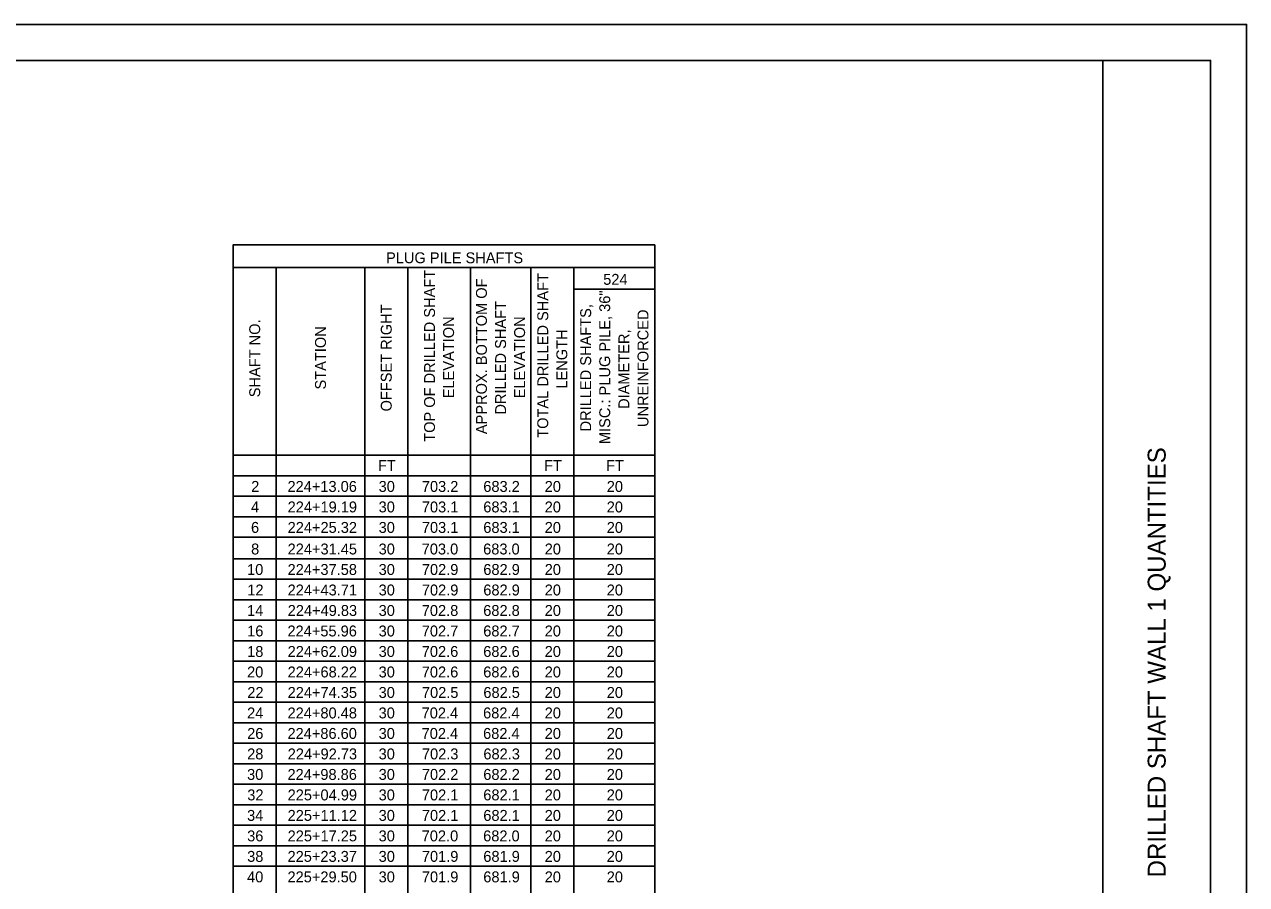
# Model space of a CAD drawing. Extents: x 0 to 34, y 0 to 22.
# Drawn here: x 17 to 34, y 10.04 to 22 of the extents above; entities that cross this region are included whole.
import ezdxf

# ---------------------------------------------------------------- set-up
doc = ezdxf.new("R2010")
doc.units = 0
for name, color, linetype in [('SH_Border', 7, 'Continuous'), ('SH_Cut_Line', 7, 'Continuous'), ('SH_Data', 7, 'Continuous'), ('SH_Text', 7, 'Continuous')]:
    doc.layers.add(name, color=color, linetype=linetype)

msp = doc.modelspace()

# ---------------------------------------------------------------- linework, layer by layer
at = {"layer": 'SH_Border'}
msp.add_line((32, 0.5), (32, 21.5), dxfattribs=at)
msp.add_lwpolyline([(1.5, 21.5), (33.5, 21.5), (33.5, 0.5), (1.5, 0.5)], close=True, dxfattribs=at)
at = {"layer": 'SH_Cut_Line'}
msp.add_lwpolyline([(0, 0), (34, 0), (34, 22), (0, 22)], close=True, dxfattribs=at)
at = {"layer": 'SH_Text'}
for p, q in [((19.903, 18.934), (25.768, 18.934)), ((19.903, 18.934), (19.903, 3.244)), ((25.768, 18.934), (25.768, 3.244)), ((19.903, 18.619), (25.768, 18.619)), ((20.503, 18.619), (20.503, 3.559)), ((21.733, 18.619), (21.733, 3.559)), ((22.333, 18.619), (22.333, 3.559)), ((23.203, 18.619), (23.203, 3.559)), ((24.043, 18.619), (24.043, 3.559)), ((24.643, 18.619), (24.643, 3.244)), ((24.643, 18.319), (25.768, 18.319)), ((19.903, 16.009), (25.768, 16.009)), ((19.903, 15.724), (25.768, 15.724)), ((19.903, 15.439), (25.768, 15.439)), ((19.903, 15.154), (25.768, 15.154)), ((19.903, 14.869), (25.768, 14.869)), ((19.903, 14.569), (25.768, 14.569)), ((19.903, 14.284), (25.768, 14.284)), ((19.903, 13.999), (25.768, 13.999)), ((19.903, 13.714), (25.768, 13.714)), ((19.903, 13.429), (25.768, 13.429)), ((19.903, 13.144), (25.768, 13.144)), ((19.903, 12.859), (25.768, 12.859)), ((19.903, 12.574), (25.768, 12.574)), ((19.903, 12.289), (25.768, 12.289)), ((19.903, 12.004), (25.768, 12.004)), ((19.903, 11.719), (25.768, 11.719)), ((19.903, 11.434), (25.768, 11.434)), ((19.903, 11.149), (25.768, 11.149)), ((19.903, 10.864), (25.768, 10.864)), ((19.903, 10.579), (25.768, 10.579)), ((19.903, 10.294), (25.768, 10.294))]:
    msp.add_line(p, q, dxfattribs=at)
for points in [[(19.903, 18.934), (19.903, 18.934), (19.903, 18.634), (19.903, 18.634)], [(19.903, 18.934), (19.903, 18.934), (19.903, 18.634), (19.903, 18.634)], [(19.903, 18.934), (19.903, 18.934), (19.903, 18.634), (19.903, 18.634)], [(19.903, 18.934), (19.903, 18.934), (19.903, 16.624), (19.903, 16.624)], [(19.903, 18.934), (19.903, 18.934), (19.903, 16.624), (19.903, 16.624)], [(19.903, 18.934), (19.903, 18.934), (19.903, 16.624), (19.903, 16.624)], [(19.903, 18.934), (19.903, 18.934), (19.903, 18.649), (19.903, 18.649)], [(19.903, 18.934), (19.903, 18.934), (19.903, 18.649), (19.903, 18.649)], [(19.903, 18.934), (19.903, 18.934), (19.903, 18.649), (19.903, 18.649)], [(19.903, 18.934), (19.903, 18.934), (19.903, 18.649), (19.903, 18.649)], [(19.903, 18.934), (19.903, 18.934), (19.903, 18.649), (19.903, 18.649)], [(19.903, 18.934), (19.903, 18.934), (19.903, 18.649), (19.903, 18.649)], [(19.903, 18.934), (19.903, 18.934), (19.903, 18.649), (19.903, 18.649)], [(19.903, 18.934), (19.903, 18.934), (19.903, 18.649), (19.903, 18.649)], [(19.903, 18.934), (19.903, 18.934), (19.903, 18.649), (19.903, 18.649)], [(19.903, 18.934), (19.903, 18.934), (19.903, 18.649), (19.903, 18.649)], [(19.903, 18.934), (19.903, 18.934), (19.903, 18.649), (19.903, 18.649)], [(19.903, 18.934), (19.903, 18.934), (19.903, 18.649), (19.903, 18.649)], [(19.903, 18.934), (19.903, 18.934), (19.903, 18.634), (19.903, 18.634)], [(19.903, 18.934), (19.903, 18.934), (19.903, 18.634), (19.903, 18.634)], [(19.903, 18.934), (19.903, 18.934), (19.903, 18.634), (19.903, 18.634)], [(19.903, 18.934), (19.903, 18.934), (19.903, 18.649), (19.903, 18.649)], [(19.903, 18.934), (19.903, 18.934), (19.903, 18.649), (19.903, 18.649)], [(19.903, 18.934), (19.903, 18.934), (19.903, 18.649), (19.903, 18.649)], [(19.903, 18.934), (19.903, 18.934), (19.903, 18.649), (19.903, 18.649)], [(19.903, 18.934), (19.903, 18.934), (19.903, 18.649), (19.903, 18.649)], [(19.903, 18.934), (19.903, 18.934), (19.903, 18.649), (19.903, 18.649)], [(19.903, 18.934), (19.903, 18.934), (19.903, 18.649), (19.903, 18.649)], [(19.903, 18.934), (19.903, 18.934), (19.903, 18.649), (19.903, 18.649)], [(19.903, 18.934), (19.903, 18.934), (19.903, 18.649), (19.903, 18.649)], [(19.903, 18.934), (19.903, 18.934), (19.903, 18.649), (19.903, 18.649)], [(19.903, 18.934), (19.903, 18.934), (19.903, 18.649), (19.903, 18.649)], [(19.903, 18.934), (19.903, 18.934), (19.903, 18.649), (19.903, 18.649)], [(19.903, 18.934), (19.903, 18.934), (19.903, 18.649), (19.903, 18.649)], [(19.903, 18.934), (19.903, 18.934), (19.903, 18.649), (19.903, 18.649)], [(19.903, 18.934), (19.903, 18.934), (19.903, 18.649), (19.903, 18.649)], [(19.903, 18.934), (19.903, 18.934), (19.903, 18.649), (19.903, 18.649)], [(19.903, 18.934), (19.903, 18.934), (19.903, 18.649), (19.903, 18.649)], [(19.903, 18.934), (19.903, 18.934), (19.903, 18.649), (19.903, 18.649)], [(19.903, 18.934), (19.903, 18.934), (19.903, 18.649), (19.903, 18.649)], [(19.903, 18.934), (19.903, 18.934), (19.903, 18.649), (19.903, 18.649)], [(19.903, 18.934), (19.903, 18.934), (19.903, 18.649), (19.903, 18.649)], [(19.903, 18.934), (19.903, 18.934), (19.903, 18.649), (19.903, 18.649)], [(19.903, 18.934), (19.903, 18.934), (19.903, 18.649), (19.903, 18.649)], [(19.903, 18.934), (19.903, 18.934), (19.903, 18.649), (19.903, 18.649)], [(19.903, 18.934), (19.903, 18.934), (19.903, 18.649), (19.903, 18.649)], [(19.903, 18.934), (19.903, 18.934), (19.903, 18.649), (19.903, 18.649)], [(19.903, 18.934), (19.903, 18.934), (19.903, 18.649), (19.903, 18.649)], [(19.903, 18.934), (19.903, 18.934), (19.903, 18.649), (19.903, 18.649)], [(19.903, 18.934), (19.903, 18.934), (19.903, 18.649), (19.903, 18.649)], [(19.903, 18.934), (19.903, 18.934), (19.903, 18.649), (19.903, 18.649)], [(19.903, 18.934), (19.903, 18.934), (19.903, 18.649), (19.903, 18.649)], [(19.903, 18.934), (19.903, 18.934), (19.903, 18.649), (19.903, 18.649)], [(19.903, 18.934), (19.903, 18.934), (19.903, 18.649), (19.903, 18.649)], [(19.903, 18.934), (19.903, 18.934), (19.903, 18.649), (19.903, 18.649)], [(19.903, 18.934), (19.903, 18.934), (19.903, 18.649), (19.903, 18.649)], [(19.903, 18.934), (19.903, 18.934), (19.903, 18.649), (19.903, 18.649)], [(19.903, 18.934), (19.903, 18.934), (19.903, 18.649), (19.903, 18.649)], [(19.903, 18.934), (19.903, 18.934), (19.903, 18.649), (19.903, 18.649)], [(19.903, 18.934), (19.903, 18.934), (19.903, 18.649), (19.903, 18.649)], [(19.903, 18.934), (19.903, 18.934), (19.903, 18.649), (19.903, 18.649)], [(19.903, 18.934), (19.903, 18.934), (19.903, 18.649), (19.903, 18.649)], [(19.903, 18.934), (19.903, 18.934), (19.903, 18.649), (19.903, 18.649)], [(19.903, 18.934), (19.903, 18.934), (19.903, 18.649), (19.903, 18.649)], [(19.903, 18.934), (19.903, 18.934), (19.903, 18.649), (19.903, 18.649)], [(19.903, 18.934), (19.903, 18.934), (19.903, 18.649), (19.903, 18.649)], [(19.903, 18.934), (19.903, 18.934), (19.903, 18.649), (19.903, 18.649)], [(19.903, 18.934), (19.903, 18.934), (19.903, 18.649), (19.903, 18.649)], [(19.903, 18.934), (19.903, 18.934), (19.903, 18.649), (19.903, 18.649)], [(19.903, 18.934), (19.903, 18.934), (19.903, 18.649), (19.903, 18.649)], [(19.903, 18.934), (19.903, 18.934), (19.903, 18.649), (19.903, 18.649)], [(19.903, 18.934), (19.903, 18.934), (19.903, 18.649), (19.903, 18.649)], [(19.903, 18.934), (19.903, 18.934), (19.903, 18.649), (19.903, 18.649)], [(19.903, 18.934), (19.903, 18.934), (19.903, 18.649), (19.903, 18.649)], [(19.903, 18.934), (19.903, 18.934), (19.903, 18.649), (19.903, 18.649)], [(19.903, 18.934), (19.903, 18.934), (19.903, 18.649), (19.903, 18.649)], [(19.903, 18.934), (19.903, 18.934), (19.903, 18.649), (19.903, 18.649)], [(19.903, 18.934), (19.903, 18.934), (19.903, 18.649), (19.903, 18.649)], [(19.903, 18.934), (19.903, 18.934), (19.903, 18.649), (19.903, 18.649)], [(19.903, 18.934), (19.903, 18.934), (19.903, 18.649), (19.903, 18.649)], [(19.903, 18.934), (19.903, 18.934), (19.903, 18.649), (19.903, 18.649)], [(19.903, 18.934), (19.903, 18.934), (19.903, 18.649), (19.903, 18.649)], [(19.903, 18.934), (19.903, 18.934), (19.903, 18.649), (19.903, 18.649)], [(19.903, 18.934), (19.903, 18.934), (19.903, 18.649), (19.903, 18.649)], [(19.903, 18.934), (19.903, 18.934), (19.903, 18.649), (19.903, 18.649)], [(19.903, 18.934), (19.903, 18.934), (19.903, 18.649), (19.903, 18.649)], [(19.903, 18.934), (19.903, 18.934), (19.903, 18.649), (19.903, 18.649)], [(19.903, 18.934), (19.903, 18.934), (19.903, 18.649), (19.903, 18.649)], [(19.903, 18.934), (19.903, 18.934), (19.903, 18.649), (19.903, 18.649)], [(19.903, 18.934), (19.903, 18.934), (19.903, 18.649), (19.903, 18.649)], [(19.903, 18.934), (19.903, 18.934), (19.903, 18.649), (19.903, 18.649)], [(19.903, 18.934), (19.903, 18.934), (19.903, 18.649), (19.903, 18.649)], [(19.903, 18.934), (19.903, 18.934), (19.903, 18.649), (19.903, 18.649)], [(19.903, 18.934), (19.903, 18.934), (19.903, 18.649), (19.903, 18.649)], [(19.903, 18.934), (19.903, 18.934), (19.903, 18.649), (19.903, 18.649)], [(19.903, 18.934), (19.903, 18.934), (19.903, 18.649), (19.903, 18.649)], [(19.903, 18.934), (19.903, 18.934), (19.903, 18.649), (19.903, 18.649)], [(19.903, 18.934), (19.903, 18.934), (19.903, 18.649), (19.903, 18.649)], [(19.903, 18.934), (19.903, 18.934), (19.903, 18.649), (19.903, 18.649)], [(19.903, 18.934), (19.903, 18.934), (19.903, 18.649), (19.903, 18.649)], [(19.903, 18.934), (19.903, 18.934), (19.903, 18.649), (19.903, 18.649)], [(19.903, 18.934), (19.903, 18.934), (19.903, 18.649), (19.903, 18.649)], [(19.903, 18.934), (19.903, 18.934), (19.903, 18.634), (19.903, 18.634)], [(19.903, 18.934), (19.903, 18.934), (19.903, 18.634), (19.903, 18.634)], [(19.903, 18.934), (19.903, 18.934), (19.903, 18.634), (19.903, 18.634)], [(19.903, 18.934), (19.903, 18.934), (19.903, 18.634), (19.903, 18.634)], [(19.903, 18.934), (19.903, 18.934), (19.903, 18.634), (19.903, 18.634)], [(19.903, 18.934), (19.903, 18.934), (19.903, 18.634), (19.903, 18.634)], [(19.903, 18.934), (19.903, 18.934), (19.903, 18.634), (19.903, 18.634)], [(19.903, 18.934), (19.903, 18.934), (19.903, 18.634), (19.903, 18.634)], [(19.903, 18.934), (19.903, 18.934), (19.903, 18.634), (19.903, 18.634)], [(19.903, 18.934), (19.903, 18.934), (19.903, 18.634), (19.903, 18.634)], [(19.903, 18.934), (19.903, 18.934), (19.903, 18.634), (19.903, 18.634)], [(19.903, 18.934), (19.903, 18.934), (19.903, 18.634), (19.903, 18.634)], [(19.903, 18.934), (19.903, 18.934), (19.903, 18.634), (19.903, 18.634)], [(19.903, 18.934), (19.903, 18.934), (19.903, 18.634), (19.903, 18.634)], [(19.903, 18.934), (19.903, 18.934), (19.903, 18.634), (19.903, 18.634)], [(19.903, 18.934), (19.903, 18.934), (19.903, 18.634), (19.903, 18.634)], [(19.903, 18.934), (19.903, 18.934), (19.903, 18.634), (19.903, 18.634)], [(19.903, 18.934), (19.903, 18.934), (19.903, 18.634), (19.903, 18.634)], [(19.903, 18.934), (19.903, 18.934), (19.903, 18.634), (19.903, 18.634)], [(19.903, 18.934), (19.903, 18.934), (19.903, 18.634), (19.903, 18.634)], [(19.903, 18.934), (19.903, 18.934), (19.903, 18.634), (19.903, 18.634)], [(19.903, 18.934), (19.903, 18.934), (19.903, 18.634), (19.903, 18.634)], [(19.903, 18.934), (19.903, 18.934), (19.903, 18.634), (19.903, 18.634)], [(19.903, 18.934), (19.903, 18.934), (19.903, 18.634), (19.903, 18.634)], [(19.903, 18.934), (19.903, 18.934), (19.903, 18.634), (19.903, 18.634)], [(19.903, 18.934), (19.903, 18.934), (19.903, 18.634), (19.903, 18.634)], [(19.903, 18.934), (19.903, 18.934), (19.903, 18.634), (19.903, 18.634)], [(19.903, 18.934), (19.903, 18.934), (19.903, 18.634), (19.903, 18.634)], [(19.903, 18.934), (19.903, 18.934), (19.903, 18.634), (19.903, 18.634)], [(19.903, 18.934), (19.903, 18.934), (19.903, 18.634), (19.903, 18.634)], [(19.903, 18.934), (19.903, 18.934), (19.903, 18.619), (19.903, 18.619)], [(19.903, 18.934), (19.903, 18.934), (19.903, 18.619), (19.903, 18.619)], [(19.903, 18.934), (19.903, 18.934), (19.903, 18.619), (19.903, 18.619)], [(19.903, 18.934), (19.903, 18.934), (19.903, 18.619), (19.903, 18.619)], [(19.903, 18.934), (19.903, 18.934), (19.903, 18.619), (19.903, 18.619)]]:
    msp.add_lwpolyline(points, close=True, dxfattribs=at)

# ---------------------------------------------------------------- texts
at = {"layer": 'SH_Data'}
msp.add_text('DRILLED SHAFT WALL 1 QUANTITIES', height=0.25, rotation=90, dxfattribs=at).set_placement((32.875, 10.138))
at = {"layer": 'SH_Text'}
for s, height, p in [('PLUG PILE SHAFTS', 0.1518, (22.03, 18.679)), ('524', 0.1518, (25.051, 18.379)), ('FT', 0.1518, (21.918, 15.791)), ('FT', 0.1518, (24.228, 15.791)), ('FT', 0.1518, (25.09, 15.791)), ('2', 0.152, (20.154, 15.499)), ('224+13.06', 0.1518, (20.659, 15.499)), ('30', 0.1518, (21.927, 15.499)), ('703.2', 0.1518, (22.528, 15.499)), ('683.2', 0.1518, (23.383, 15.499)), ('20', 0.1518, (24.237, 15.499)), ('20', 0.1518, (25.1, 15.499)), ('4', 0.152, (20.151, 15.214)), ('224+19.19', 0.1518, (20.661, 15.214)), ('30', 0.1518, (21.927, 15.214)), ('703.1', 0.1518, (22.528, 15.214)), ('683.1', 0.1518, (23.383, 15.214)), ('20', 0.1518, (24.237, 15.214)), ('20', 0.1518, (25.1, 15.214)), ('6', 0.152, (20.152, 14.929)), ('224+25.32', 0.1518, (20.661, 14.929)), ('30', 0.1518, (21.927, 14.929)), ('703.1', 0.1518, (22.528, 14.929)), ('683.1', 0.1518, (23.383, 14.929)), ('20', 0.1518, (24.237, 14.929)), ('20', 0.1518, (25.1, 14.929)), ('8', 0.152, (20.153, 14.629)), ('224+31.45', 0.1518, (20.661, 14.629)), ('30', 0.1518, (21.927, 14.629)), ('703.0', 0.1518, (22.526, 14.629)), ('683.0', 0.1518, (23.381, 14.629)), ('20', 0.1518, (24.237, 14.629)), ('20', 0.1518, (25.1, 14.629)), ('10', 0.1518, (20.097, 14.344)), ('224+37.58', 0.1518, (20.66, 14.344)), ('30', 0.1518, (21.927, 14.344)), ('702.9', 0.1518, (22.528, 14.344)), ('682.9', 0.1518, (23.383, 14.344)), ('20', 0.1518, (24.237, 14.344)), ('20', 0.1518, (25.1, 14.344)), ('12', 0.1518, (20.1, 14.059)), ('224+43.71', 0.1518, (20.661, 14.059)), ('30', 0.1518, (21.927, 14.059)), ('702.9', 0.1518, (22.528, 14.059)), ('682.9', 0.1518, (23.383, 14.059)), ('20', 0.1518, (24.237, 14.059)), ('20', 0.1518, (25.1, 14.059)), ('14', 0.1518, (20.097, 13.774)), ('224+49.83', 0.1518, (20.662, 13.774)), ('30', 0.1518, (21.927, 13.774)), ('702.8', 0.1518, (22.527, 13.774)), ('682.8', 0.1518, (23.382, 13.774)), ('20', 0.1518, (24.237, 13.774)), ('20', 0.1518, (25.1, 13.774)), ('16', 0.1518, (20.098, 13.489)), ('224+55.96', 0.1518, (20.659, 13.489)), ('30', 0.1518, (21.927, 13.489)), ('702.7', 0.1518, (22.527, 13.489)), ('682.7', 0.1518, (23.382, 13.489)), ('20', 0.1518, (24.237, 13.489)), ('20', 0.1518, (25.1, 13.489)), ('18', 0.1518, (20.098, 13.204)), ('224+62.09', 0.1518, (20.661, 13.204)), ('30', 0.1518, (21.927, 13.204)), ('702.6', 0.1518, (22.527, 13.204)), ('682.6', 0.1518, (23.382, 13.204)), ('20', 0.1518, (24.237, 13.204)), ('20', 0.1518, (25.1, 13.204)), ('20', 0.1518, (20.097, 12.919)), ('224+68.22', 0.1518, (20.661, 12.919)), ('30', 0.1518, (21.927, 12.919)), ('702.6', 0.1518, (22.527, 12.919)), ('682.6', 0.1518, (23.382, 12.919)), ('20', 0.1518, (24.237, 12.919)), ('20', 0.1518, (25.1, 12.919)), ('22', 0.1518, (20.1, 12.634)), ('224+74.35', 0.1518, (20.661, 12.634)), ('30', 0.1518, (21.927, 12.634)), ('702.5', 0.1518, (22.529, 12.634)), ('682.5', 0.1518, (23.384, 12.634)), ('20', 0.1518, (24.237, 12.634)), ('20', 0.1518, (25.1, 12.634)), ('24', 0.1518, (20.097, 12.349)), ('224+80.48', 0.1518, (20.66, 12.349)), ('30', 0.1518, (21.927, 12.349)), ('702.4', 0.1518, (22.525, 12.349)), ('682.4', 0.1518, (23.38, 12.349)), ('20', 0.1518, (24.237, 12.349)), ('20', 0.1518, (25.1, 12.349)), ('26', 0.1518, (20.098, 12.064)), ('224+86.60', 0.1518, (20.659, 12.064)), ('30', 0.1518, (21.927, 12.064)), ('702.4', 0.1518, (22.525, 12.064)), ('682.4', 0.1518, (23.38, 12.064)), ('20', 0.1518, (24.237, 12.064)), ('20', 0.1518, (25.1, 12.064)), ('28', 0.1518, (20.098, 11.779)), ('224+92.73', 0.1518, (20.662, 11.779)), ('30', 0.1518, (21.927, 11.779)), ('702.3', 0.1518, (22.529, 11.779)), ('682.3', 0.1518, (23.384, 11.779)), ('20', 0.1518, (24.237, 11.779)), ('20', 0.1518, (25.1, 11.779)), ('30', 0.1518, (20.097, 11.494)), ('224+98.86', 0.1518, (20.659, 11.494)), ('30', 0.1518, (21.927, 11.494)), ('702.2', 0.1518, (22.528, 11.494)), ('682.2', 0.1518, (23.383, 11.494)), ('20', 0.1518, (24.237, 11.494)), ('20', 0.1518, (25.1, 11.494)), ('32', 0.1518, (20.1, 11.209)), ('225+04.99', 0.1518, (20.661, 11.209)), ('30', 0.1518, (21.927, 11.209)), ('702.1', 0.1518, (22.528, 11.209)), ('682.1', 0.1518, (23.383, 11.209)), ('20', 0.1518, (24.237, 11.209)), ('20', 0.1518, (25.1, 11.209)), ('34', 0.1518, (20.097, 10.924)), ('225+11.12', 0.1518, (20.661, 10.924)), ('30', 0.1518, (21.927, 10.924)), ('702.1', 0.1518, (22.528, 10.924)), ('682.1', 0.1518, (23.383, 10.924)), ('20', 0.1518, (24.237, 10.924)), ('20', 0.1518, (25.1, 10.924)), ('36', 0.1518, (20.098, 10.639)), ('225+17.25', 0.1518, (20.661, 10.639)), ('30', 0.1518, (21.927, 10.639)), ('702.0', 0.1518, (22.526, 10.639)), ('682.0', 0.1518, (23.381, 10.639)), ('20', 0.1518, (24.237, 10.639)), ('20', 0.1518, (25.1, 10.639)), ('38', 0.1518, (20.098, 10.354)), ('225+23.37', 0.1518, (20.66, 10.354)), ('30', 0.1518, (21.927, 10.354)), ('701.9', 0.1518, (22.528, 10.354)), ('681.9', 0.1518, (23.383, 10.354)), ('20', 0.1518, (24.237, 10.354)), ('20', 0.1518, (25.1, 10.354)), ('40', 0.1518, (20.097, 10.069)), ('225+29.50', 0.1518, (20.659, 10.069)), ('30', 0.1518, (21.927, 10.069)), ('701.9', 0.1518, (22.528, 10.069)), ('681.9', 0.1518, (23.383, 10.069)), ('20', 0.1518, (24.237, 10.069)), ('20', 0.1518, (25.1, 10.069))]:
    msp.add_text(s, height=height, dxfattribs=at).set_placement(p)
for s, p in [('TOP OF DRILLED SHAFT ', (22.711, 16.196)), ('TOTAL DRILLED SHAFT ', (24.286, 16.252)), ('APPROX. BOTTOM OF ', (23.433, 16.302)), ('MISC.: PLUG PILE, 36" ', (25.148, 16.164)), ('OFFSET RIGHT', (22.109, 16.618)), ('DRILLED SHAFT ', (23.699, 16.574)), ('DRILLED SHAFTS, ', (24.883, 16.34)), ('UNREINFORCED', (25.68, 16.401)), ('SHAFT NO.', (20.279, 16.815)), ('ELEVATION', (22.976, 16.801)), ('ELEVATION', (23.964, 16.801)), ('STATION', (21.194, 16.923)), ('LENGTH', (24.551, 16.935)), ('DIAMETER, ', (25.414, 16.653))]:
    msp.add_text(s, height=0.1518, rotation=90, dxfattribs=at).set_placement(p)

doc.saveas('drawing.dxf')
